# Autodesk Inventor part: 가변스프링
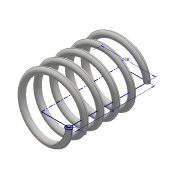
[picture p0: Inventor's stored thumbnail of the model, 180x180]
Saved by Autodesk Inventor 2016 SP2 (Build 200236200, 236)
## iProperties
Created: 2017-12
Part Number: 가변스프링
Material: Generic
Document SubType Name: Modeling
Designer: Administrator
Density: 1 g/cm^3
Appearance: Default
Author: Administrator
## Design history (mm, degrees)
sketch "스케치1"
  geometry: L1 (0, 0)-(9, 0); L2 (9, 0)-(9, 26); L3 (9, 26)-(0, 26); L4 (0, 26)-(0, 0); C1 r 1 at (9, 0)
  constraints: 8 end point, 2 parallel, 1 centre point, 1 coincident, 1 horizontal, 1 perpendicular
  dimensions: "d0" = 2 diameter of C1; "d1" = 26 distance of L1.end L2.end; "d2" = 18 diameter of L2 L4
feature "코일1" pitch "d3" = 10; turns "d5" = 5; dims "d4" = 26 (= d1), "d6" = 0, angle "d7" = 90 deg, angle "d8" = 90 deg, "d9" = 0, "d10" = 0
sketch "스케치2"
  geometry: L1 (-10, 0)-(-8, 0) reference; 1 further point
  constraints: 1 horizontal alignment
extrude "돌출1" cut sketch "스케치2" stored distance "d11" = 10; taper "d12" = 0 deg
node "작업 평면1"
sketch "스케치3"
  geometry: L1 (1, 0)-(-1, 0) reference; 1 further point
  constraints: 1 horizontal alignment
extrude "돌출2" cut sketch "스케치3" stored distance "d14" = 10; taper "d15" = 0 deg
node "솔리드1"
node "절단 모서리 투영1"
node "절단 모서리 투영2"
other parameters: "d13" = 90 deg
